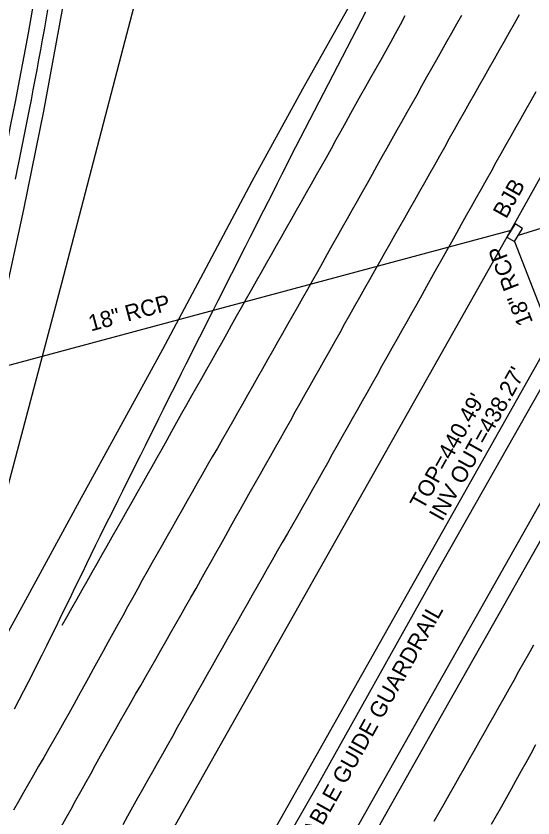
# Model space of a CAD drawing. Extents: x 2074109 to 2077820, y 741079 to 746031.
# Drawn here: x 2075088.5 to 2075216, y 742680.2 to 742877.9 of the extents above; entities that cross this region are included whole.
import ezdxf

# ---------------------------------------------------------------- set-up
doc = ezdxf.new("R2010")
doc.units = 0
for name, color, linetype in [('Exist Guardrail Cable Guide Rail', 7, 'Continuous'), ('Exist Guardrail Cable Guide Rail Text', 7, 'Continuous'), ('Exist Horizontal Alignment', 7, 'Continuous'), ('Exist Roads EOP', 7, 'Continuous'), ('Exist Roads EOT', 7, 'Continuous'), ('Exist Structure Minor Drop Inlet Top Elevation', 7, 'Continuous'), ('Exist Structure Minor Junction Box', 7, 'Continuous'), ('Exist Structure Minor Junction Box Text', 7, 'Continuous'), ('Exist Structure Minor Pipes RCP 18 Inch', 7, 'Continuous'), ('Exist Structure Minor Pipes RCP 18 Inch Invert', 7, 'Continuous'), ('Exist Structure Minor Pipes RCP 18 Inch Text', 7, 'Continuous'), ('Exist Structure Minor Pipes RCP 30 Inch', 7, 'Continuous'), ('Exist Utilities Telephone UG FO SUE LOS B', 7, 'Continuous')]:
    doc.layers.add(name, color=color, linetype=linetype)

msp = doc.modelspace()

# ---------------------------------------------------------------- linework, layer by layer
at = {"layer": 'Exist Guardrail Cable Guide Rail'}
msp.add_lwpolyline([(2075043.78, 742487.09), (2075058.56, 742508.52), (2075082.64, 742547.78), (2075110.14, 742595.62), (2075138.25, 742645.19), (2075162.9, 742688.2), (2075192.42, 742740.98), (2075230.21, 742807.65)], dxfattribs=at)
at = {"layer": 'Exist Horizontal Alignment'}
msp.add_line((2074886.11, 742205.34), (2075575.25, 743427.42), dxfattribs=at)
msp.add_arc((2073627.89, 743142.05), 1488.08, 344.52743, 358.66892, dxfattribs=at)
at = {"layer": 'Exist Roads EOP'}
for points in [[(2075082.27, 742583.2), (2075090.46, 742602.42), (2075097.51, 742619.27), (2075103.18, 742632.87), (2075107.04, 742641.29), (2075110.49, 742647.54), (2075117.02, 742659.24), (2075126.42, 742676.04), (2075137.8, 742696.19), (2075150.38, 742718.4), (2075162.39, 742739.69), (2075174.19, 742760.67), (2075186.87, 742783.1), (2075199.9, 742806.12), (2075211.88, 742827.44), (2075223.21, 742847.7), (2075235.01, 742868.73), (2075246.83, 742889.73)], [(2075297.48, 742890.45), (2075284.83, 742867.93), (2075269.65, 742840.85), (2075253.28, 742811.72), (2075237.58, 742783.58), (2075222.02, 742755.92), (2075207.65, 742730.63), (2075195.18, 742708.56), (2075181.14, 742683.69), (2075166.05, 742656.95), (2075153.79, 742635.53), (2075144.79, 742622.27), (2075137.94, 742612.64), (2075128.78, 742600.5), (2075119.38, 742587.81), (2075112.7, 742578.93), (2075100.64, 742561.46), (2075086.67, 742540.76)], [(2075085.4, 742807.04), (2075090.46, 742830.25), (2075095.34, 742854.45), (2075100.89, 742884.52)], [(2075171.5, 742881.81), (2075159.15, 742859.88), (2075146.66, 742837.14), (2075134.66, 742814.51), (2075124.64, 742795.69), (2075104.11, 742758.19), (2075090.89, 742733.91), (2075078.38, 742711.18)]]:
    msp.add_lwpolyline(points, dxfattribs=at)
at = {"layer": 'Exist Roads EOT'}
for points in [[(2075088.12, 742707.12), (2075089.31, 742709.32), (2075090.45, 742711.54), (2075091.59, 742713.76), (2075092.72, 742715.99), (2075093.85, 742718.22), (2075094.98, 742720.45), (2075096.11, 742722.68), (2075097.21, 742724.93), (2075098.31, 742727.17), (2075099.4, 742729.42), (2075100.5, 742731.67), (2075101.59, 742733.91), (2075102.69, 742736.16), (2075103.78, 742738.41), (2075104.88, 742740.66), (2075105.97, 742742.9), (2075107.07, 742745.15), (2075108.16, 742747.4), (2075109.26, 742749.64), (2075110.36, 742751.89), (2075111.48, 742754.12), (2075112.6, 742756.36), (2075113.72, 742758.59), (2075114.83, 742760.83), (2075115.95, 742763.07), (2075117.07, 742765.3), (2075118.18, 742767.54), (2075119.3, 742769.77), (2075120.42, 742772.01), (2075121.53, 742774.25), (2075122.65, 742776.48), (2075123.77, 742778.72), (2075124.89, 742780.96), (2075126, 742783.19), (2075127.12, 742785.43), (2075128.24, 742787.66), (2075129.36, 742789.9), (2075130.49, 742792.13), (2075131.61, 742794.36), (2075132.74, 742796.59), (2075133.86, 742798.82), (2075134.99, 742801.06), (2075136.11, 742803.29), (2075137.24, 742805.52), (2075138.37, 742807.75), (2075139.49, 742809.98), (2075140.62, 742812.22), (2075141.74, 742814.45), (2075142.87, 742816.68), (2075144, 742818.91), (2075145.13, 742821.14), (2075146.25, 742823.37), (2075147.38, 742825.6), (2075148.51, 742827.83), (2075149.64, 742830.06), (2075150.77, 742832.29), (2075151.9, 742834.52), (2075153.03, 742836.75), (2075154.16, 742838.98), (2075155.29, 742841.21), (2075156.42, 742843.44), (2075157.57, 742845.66), (2075158.71, 742847.88), (2075159.85, 742850.11), (2075160.99, 742852.33), (2075162.13, 742854.55), (2075163.28, 742856.78), (2075164.42, 742859), (2075165.56, 742861.23), (2075166.71, 742863.45), (2075167.86, 742865.66), (2075169.01, 742867.88), (2075170.17, 742870.1), (2075171.32, 742872.32), (2075172.47, 742874.53), (2075173.63, 742876.75), (2075174.78, 742878.97)], [(2075088.41, 742837.69), (2075088.9, 742840.14), (2075089.39, 742842.59), (2075089.88, 742845.04), (2075090.37, 742847.49), (2075090.86, 742849.94), (2075091.35, 742852.4), (2075091.84, 742854.85), (2075092.3, 742857.3), (2075092.77, 742859.76), (2075093.23, 742862.22), (2075093.7, 742864.67), (2075094.17, 742867.13), (2075094.63, 742869.58), (2075095.07, 742872.05), (2075095.51, 742874.51), (2075095.94, 742876.97), (2075096.38, 742879.43)], [(2075198.36, 742878.07), (2075197.14, 742875.89), (2075195.92, 742873.71), (2075194.7, 742871.53), (2075193.47, 742869.35), (2075192.24, 742867.17), (2075191.02, 742865), (2075189.79, 742862.82), (2075188.56, 742860.64), (2075187.34, 742858.46), (2075186.11, 742856.28), (2075184.88, 742854.11), (2075183.66, 742851.93), (2075182.43, 742849.75), (2075181.2, 742847.57), (2075179.98, 742845.39), (2075178.76, 742843.21), (2075177.54, 742841.03), (2075176.32, 742838.84), (2075175.1, 742836.67), (2075173.87, 742834.49), (2075172.65, 742832.31), (2075171.42, 742830.13), (2075170.2, 742827.95), (2075168.97, 742825.77), (2075167.74, 742823.6), (2075166.52, 742821.42), (2075165.29, 742819.24), (2075164.07, 742817.06), (2075162.84, 742814.88), (2075161.62, 742812.7), (2075160.38, 742810.53), (2075159.15, 742808.35), (2075157.92, 742806.18), (2075156.69, 742804), (2075155.45, 742801.83), (2075154.22, 742799.65), (2075152.99, 742797.48), (2075151.76, 742795.3), (2075150.53, 742793.13), (2075149.3, 742790.95), (2075148.07, 742788.78), (2075146.84, 742786.6), (2075145.61, 742784.42), (2075144.38, 742782.25), (2075143.15, 742780.07), (2075141.91, 742777.9), (2075140.67, 742775.73), (2075139.42, 742773.56), (2075138.17, 742771.4), (2075136.92, 742769.23), (2075135.69, 742767.06), (2075134.45, 742764.89), (2075133.22, 742762.71), (2075131.99, 742760.54), (2075130.75, 742758.36), (2075129.52, 742756.19), (2075128.28, 742754.02), (2075127.05, 742751.84), (2075125.82, 742749.67), (2075124.58, 742747.49), (2075123.35, 742745.32), (2075122.12, 742743.15), (2075120.89, 742740.97), (2075119.67, 742738.79), (2075118.45, 742736.61), (2075117.23, 742734.42), (2075116.02, 742732.23), (2075114.82, 742730.04), (2075113.61, 742727.86), (2075112.4, 742725.67), (2075111.2, 742723.48), (2075109.99, 742721.29), (2075108.78, 742719.1), (2075107.58, 742716.91), (2075106.37, 742714.72), (2075105.16, 742712.53), (2075103.96, 742710.34), (2075102.75, 742708.16), (2075101.51, 742705.98), (2075100.28, 742703.81), (2075099.05, 742701.63), (2075097.82, 742699.46), (2075096.58, 742697.29), (2075095.34, 742695.11), (2075094.1, 742692.94), (2075092.86, 742690.77), (2075091.62, 742688.6), (2075090.38, 742686.43), (2075089.14, 742684.26), (2075087.91, 742682.09)], [(2075099.65, 742678.01), (2075100.86, 742680.19), (2075102.08, 742682.37), (2075103.29, 742684.56), (2075104.51, 742686.74), (2075105.72, 742688.93), (2075106.94, 742691.11), (2075108.16, 742693.29), (2075109.37, 742695.48), (2075110.6, 742697.65), (2075111.83, 742699.83), (2075113.06, 742702.01), (2075114.3, 742704.18), (2075115.54, 742706.35), (2075116.78, 742708.52), (2075118.02, 742710.69), (2075119.26, 742712.86), (2075120.5, 742715.03), (2075121.74, 742717.2), (2075122.98, 742719.37), (2075124.22, 742721.54), (2075125.47, 742723.71), (2075126.71, 742725.88), (2075127.95, 742728.05), (2075129.19, 742730.22), (2075130.43, 742732.39), (2075131.67, 742734.56), (2075132.91, 742736.73), (2075134.13, 742738.91), (2075135.35, 742741.09), (2075136.57, 742743.27), (2075137.79, 742745.45), (2075139.01, 742747.64), (2075140.23, 742749.82), (2075141.45, 742752), (2075142.67, 742754.18), (2075143.89, 742756.36), (2075145.11, 742758.54), (2075146.33, 742760.73), (2075147.55, 742762.91), (2075148.78, 742765.08), (2075150.02, 742767.25), (2075151.26, 742769.42), (2075152.5, 742771.6), (2075153.73, 742773.77), (2075154.95, 742775.95), (2075156.18, 742778.13), (2075157.4, 742780.31), (2075158.63, 742782.49), (2075159.85, 742784.67), (2075161.08, 742786.85), (2075162.3, 742789.03), (2075163.53, 742791.2), (2075164.75, 742793.38), (2075165.98, 742795.56), (2075167.2, 742797.74), (2075168.43, 742799.92), (2075169.65, 742802.1), (2075170.88, 742804.28), (2075172.1, 742806.46), (2075173.33, 742808.63), (2075174.56, 742810.81), (2075175.79, 742812.98), (2075177.02, 742815.16), (2075178.25, 742817.34), (2075179.49, 742819.51), (2075180.72, 742821.69), (2075181.95, 742823.86), (2075183.18, 742826.04), (2075184.41, 742828.21), (2075185.64, 742830.39), (2075186.87, 742832.56), (2075188.1, 742834.74), (2075189.33, 742836.92), (2075190.56, 742839.1), (2075191.78, 742841.27), (2075193.01, 742843.45), (2075194.24, 742845.63), (2075195.46, 742847.81), (2075196.69, 742849.99), (2075197.92, 742852.16), (2075199.14, 742854.34), (2075200.37, 742856.52), (2075201.6, 742858.7), (2075202.82, 742860.88), (2075204.05, 742863.05), (2075205.28, 742865.23), (2075206.5, 742867.41), (2075207.74, 742869.58), (2075208.98, 742871.75), (2075210.23, 742873.92), (2075211.47, 742876.09), (2075212.69, 742878.27)], [(2075099.92, 742727.73), (2075101.15, 742729.9), (2075102.38, 742732.08), (2075103.62, 742734.25), (2075104.85, 742736.43), (2075106.08, 742738.6), (2075107.32, 742740.77), (2075108.55, 742742.95), (2075109.78, 742745.12), (2075111.02, 742747.3), (2075112.25, 742749.47), (2075113.48, 742751.65), (2075114.72, 742753.82), (2075115.95, 742755.99), (2075117.18, 742758.17), (2075118.42, 742760.34), (2075119.65, 742762.52), (2075120.88, 742764.69), (2075122.12, 742766.86), (2075123.34, 742769.05), (2075124.55, 742771.23), (2075125.77, 742773.42), (2075126.98, 742775.6), (2075128.19, 742777.79), (2075129.41, 742779.97), (2075130.64, 742782.15), (2075131.87, 742784.32), (2075133.11, 742786.5), (2075134.34, 742788.67), (2075135.57, 742790.85), (2075136.8, 742793.02), (2075138.03, 742795.2), (2075139.25, 742797.38), (2075140.48, 742799.56), (2075141.7, 742801.74), (2075142.93, 742803.91), (2075144.15, 742806.09), (2075145.38, 742808.27), (2075146.61, 742810.45), (2075147.83, 742812.63), (2075149.06, 742814.81), (2075150.28, 742816.99), (2075151.51, 742819.16), (2075152.74, 742821.34), (2075153.97, 742823.52), (2075155.2, 742825.69), (2075156.43, 742827.87), (2075157.66, 742830.05), (2075158.89, 742832.22), (2075160.12, 742834.39), (2075161.36, 742836.57), (2075162.6, 742838.74), (2075163.83, 742840.91), (2075165.07, 742843.08), (2075166.3, 742845.26), (2075167.51, 742847.45), (2075168.72, 742849.64), (2075169.93, 742851.82), (2075171.13, 742854.01), (2075172.34, 742856.2), (2075173.55, 742858.39), (2075174.78, 742860.56), (2075176.01, 742862.74), (2075177.24, 742864.92), (2075178.47, 742867.09), (2075179.7, 742869.27), (2075180.93, 742871.45), (2075182.12, 742873.64), (2075183.32, 742875.84), (2075184.51, 742878.03)], [(2075216.75, 742859.21), (2075215.52, 742857.03), (2075214.29, 742854.86), (2075213.06, 742852.68), (2075211.83, 742850.51), (2075210.59, 742848.33), (2075209.36, 742846.15), (2075208.13, 742843.98), (2075206.9, 742841.8), (2075205.68, 742839.62), (2075204.46, 742837.44), (2075203.23, 742835.26), (2075202.01, 742833.08), (2075200.79, 742830.9), (2075199.57, 742828.72), (2075198.34, 742826.54), (2075197.12, 742824.36), (2075195.9, 742822.18), (2075194.68, 742820), (2075193.46, 742817.82), (2075192.23, 742815.64), (2075191.01, 742813.46), (2075189.79, 742811.28), (2075188.57, 742809.1), (2075187.34, 742806.92), (2075186.12, 742804.74), (2075184.9, 742802.56), (2075183.67, 742800.38), (2075182.45, 742798.2), (2075181.22, 742796.02), (2075180, 742793.84), (2075178.77, 742791.66), (2075177.55, 742789.48), (2075176.32, 742787.3), (2075175.1, 742785.12), (2075173.88, 742782.94), (2075172.65, 742780.77), (2075171.43, 742778.59), (2075170.2, 742776.41), (2075168.98, 742774.23), (2075167.75, 742772.05), (2075166.53, 742769.87), (2075165.31, 742767.69), (2075164.08, 742765.51), (2075162.86, 742763.33), (2075161.63, 742761.15), (2075160.39, 742758.98), (2075159.15, 742756.81), (2075157.91, 742754.64), (2075156.68, 742752.47), (2075155.44, 742750.3), (2075154.2, 742748.13), (2075152.96, 742745.95), (2075151.72, 742743.78), (2075150.49, 742741.61), (2075149.25, 742739.44), (2075148.01, 742737.27), (2075146.77, 742735.1), (2075145.53, 742732.92), (2075144.3, 742730.75), (2075143.06, 742728.58), (2075141.82, 742726.41), (2075140.58, 742724.24), (2075139.34, 742722.07), (2075138.11, 742719.89), (2075136.87, 742717.72), (2075135.64, 742715.54), (2075134.42, 742713.37), (2075133.19, 742711.19), (2075131.97, 742709.01), (2075130.75, 742706.83), (2075129.52, 742704.65), (2075128.3, 742702.47), (2075127.07, 742700.29), (2075125.85, 742698.11), (2075124.62, 742695.93), (2075123.4, 742693.75), (2075122.18, 742691.57), (2075120.95, 742689.39), (2075119.73, 742687.21), (2075118.5, 742685.03), (2075117.28, 742682.85), (2075116.05, 742680.67), (2075114.83, 742678.49)], [(2075191.65, 742679.36), (2075192.88, 742681.54), (2075194.11, 742683.71), (2075195.34, 742685.89), (2075196.57, 742688.06), (2075197.81, 742690.24), (2075199.04, 742692.41), (2075200.27, 742694.59), (2075201.5, 742696.76), (2075202.74, 742698.94), (2075203.97, 742701.11), (2075205.2, 742703.29), (2075206.43, 742705.46), (2075207.66, 742707.64), (2075208.88, 742709.82), (2075210.11, 742711.99), (2075211.34, 742714.17), (2075212.57, 742716.35), (2075213.79, 742718.53), (2075215.02, 742720.7), (2075216.25, 742722.88)], [(2075216.67, 742698.18), (2075215.46, 742695.99), (2075214.24, 742693.81), (2075213.03, 742691.62), (2075211.81, 742689.44), (2075210.6, 742687.25), (2075209.38, 742685.07), (2075208.17, 742682.89), (2075206.93, 742680.71), (2075205.69, 742678.54)]]:
    msp.add_lwpolyline(points, dxfattribs=at)
at = {"layer": 'Exist Structure Minor Junction Box'}
msp.add_lwpolyline([(2075211.59, 742826.69), (2075209.6, 742823.44), (2075211.47, 742822.3), (2075213.45, 742825.56)], close=True, dxfattribs=at)
at = {"layer": 'Exist Structure Minor Pipes RCP 18 Inch'}
for p, q in [((2075212.46, 742823.93), (2075264.27, 742840.07)), ((2075210.59, 742825.07), (2075042.1, 742779.83)), ((2075211.47, 742822.3), (2075220.31, 742799.59))]:
    msp.add_line(p, q, dxfattribs=at)
at = {"layer": 'Exist Structure Minor Pipes RCP 30 Inch'}
msp.add_line((2074933.64, 742254.78), (2075264.27, 742840.07), dxfattribs=at)
at = {"layer": 'Exist Utilities Telephone UG FO SUE LOS B'}
msp.add_lwpolyline([(2074932.06, 742469.18), (2074970.24, 742541.68), (2074979.51, 742559.72), (2075041.4, 742658.47), (2075061.37, 742697.95), (2075083.3, 742749.99), (2075099.82, 742812.07), (2075115.43, 742871.87), (2075127.7, 742918.57)], dxfattribs=at)

# ---------------------------------------------------------------- texts
at = {"layer": 'Exist Guardrail Cable Guide Rail Text'}
msp.add_text('CABLE GUIDE GUARDRAIL', height=4, rotation=60.7746, dxfattribs=at).set_placement((2075160.49, 742671.61))
at = {"layer": 'Exist Structure Minor Drop Inlet Top Elevation'}
msp.add_text("TOP=440.49'", height=4, rotation=60.7411, dxfattribs=at).set_placement((2075188.93, 742755.95))
at = {"layer": 'Exist Structure Minor Junction Box Text'}
msp.add_text('BJB', height=4, rotation=60.7411, dxfattribs=at).set_placement((2075209.41, 742827.75))
at = {"layer": 'Exist Structure Minor Pipes RCP 18 Inch Invert'}
msp.add_text("INV OUT=438.27'", height=4, rotation=60.7411, dxfattribs=at).set_placement((2075193.66, 742753.12))
at = {"layer": 'Exist Structure Minor Pipes RCP 18 Inch Text'}
for rotation, p in [(111.2675, (2075216.08, 742802.44)), (15.0264, (2075106.99, 742800.15))]:
    msp.add_text('18" RCP', height=4, rotation=rotation, dxfattribs=at).set_placement(p)

doc.saveas('drawing.dxf')
